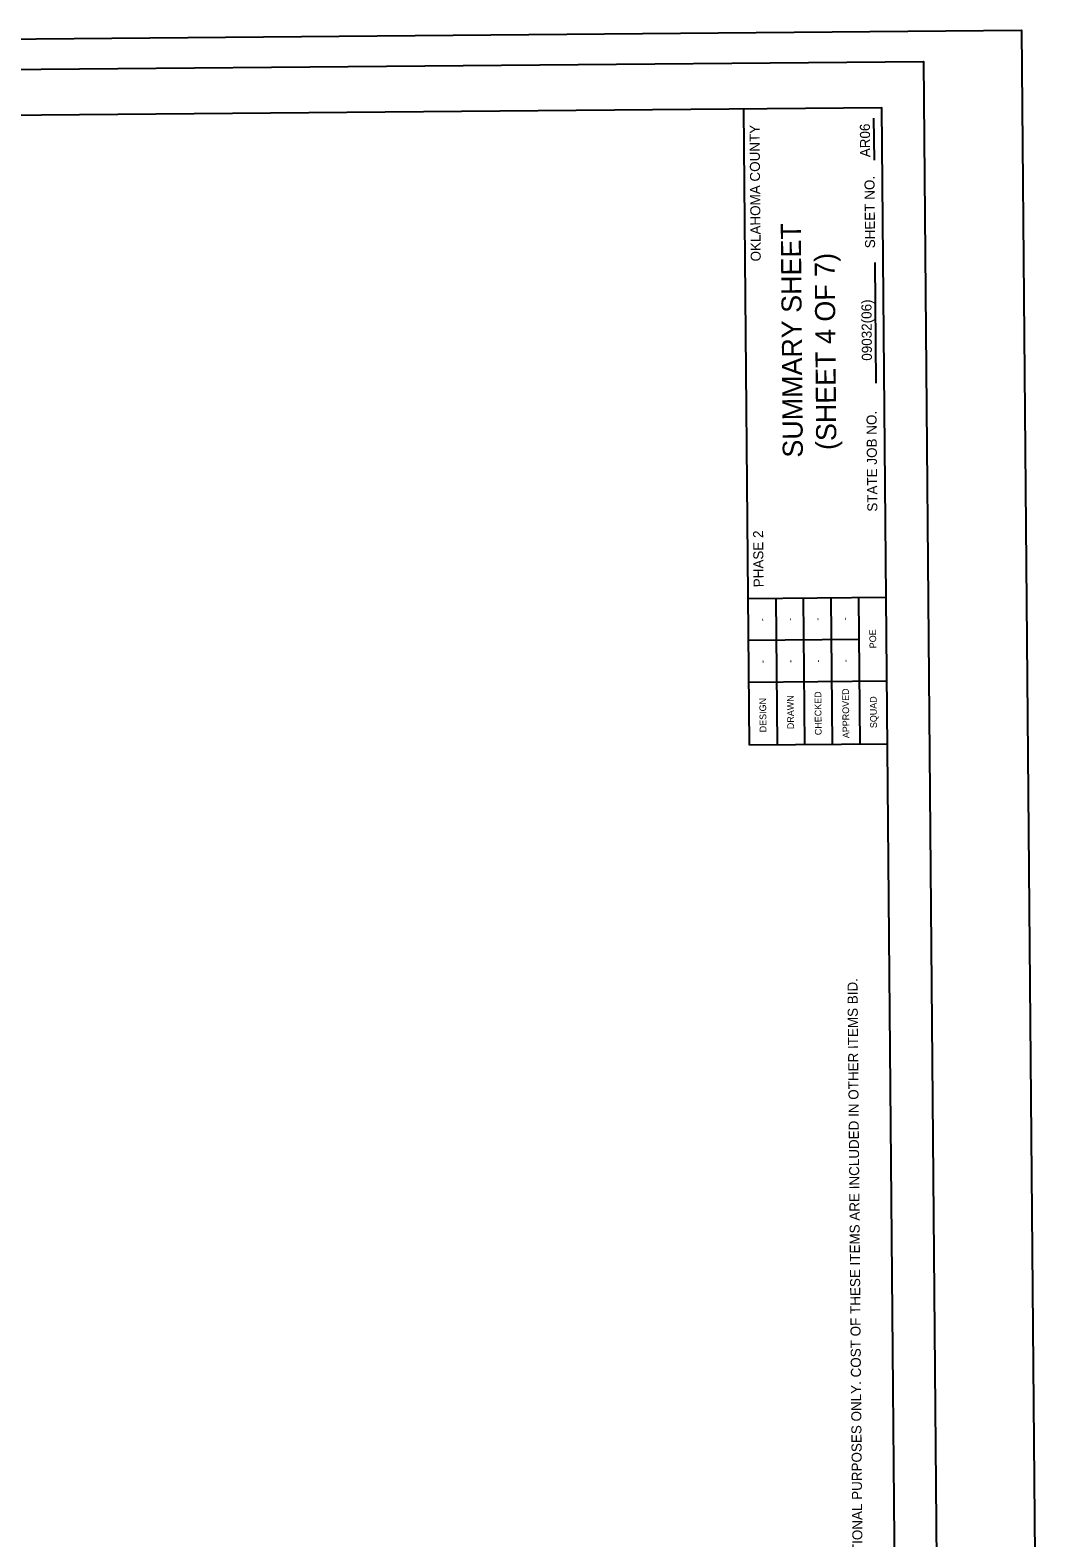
# Model space of a CAD drawing. Extents: x 2151900 to 2151925, y 142567 to 142723.
# Drawn here: x 2151912.93 to 2151925.09, y 142585.4 to 142603.41 of the extents above; entities that cross this region are included whole.
import ezdxf

# ---------------------------------------------------------------- set-up
doc = ezdxf.new("R2010")
doc.units = 0
for name, color, linetype in [('SHT_Plot_Shape_Full', 7, 'Continuous'), ('SHT_Plot_Shape_Half', 7, 'Continuous'), ('SHT_Sheet_Border', 7, 'Continuous'), ('SHT_Standard_Sheet_Lines', 7, 'Continuous'), ('SHT_Standard_Sheet_Txt', 7, 'Continuous'), ('TYP_Typical_Section_Txt', 7, 'Continuous')]:
    doc.layers.add(name, color=color, linetype=linetype)

msp = doc.modelspace()

# ---------------------------------------------------------------- linework, layer by layer
at = {"layer": 'SHT_Plot_Shape_Full'}
msp.add_lwpolyline([(2151901.092, 142567.2), (2151900.777, 142603.199), (2151924.776, 142603.409), (2151925.091, 142567.41)], close=True, dxfattribs=at)
at = {"layer": 'SHT_Plot_Shape_Half'}
msp.add_lwpolyline([(2151901.903, 142568.845), (2151901.605, 142602.844), (2151923.604, 142603.036), (2151923.902, 142569.037)], close=True, dxfattribs=at)
at = {"layer": 'SHT_Sheet_Border'}
for p, q in [((2151921.526, 142594.868), (2151921.459, 142602.467)), ((2151923.16, 142596.632), (2151921.51, 142596.617)), ((2151923.176, 142594.882), (2151921.526, 142594.868))]:
    msp.add_line(p, q, dxfattribs=at)
msp.add_lwpolyline([(2151923.385, 142570.983), (2151923.109, 142602.482), (2151902.11, 142602.298), (2151902.386, 142570.799)], close=True, dxfattribs=at)
at = {"layer": 'SHT_Standard_Sheet_Lines'}
for p, q in [((2151923.019, 142601.856), (2151923.014, 142602.359)), ((2151923.042, 142599.192), (2151923.029, 142600.632)), ((2151922.835, 142596.129), (2151921.514, 142596.118)), ((2151923.169, 142595.632), (2151921.518, 142595.618))]:
    msp.add_line(p, q, dxfattribs=at)
for points in [[(2151921.84, 142596.62), (2151921.856, 142594.871)], [(2151922.17, 142596.623), (2151922.186, 142594.873)], [(2151922.5, 142596.626), (2151922.516, 142594.876)], [(2151922.83, 142596.629), (2151922.846, 142594.879)]]:
    msp.add_lwpolyline(points, dxfattribs=at)

# ---------------------------------------------------------------- texts
at = {"layer": 'SHT_Standard_Sheet_Txt'}
for s, height, p in [('OKLAHOMA COUNTY', 0.12, (2151921.662, 142600.647)), ('AR06', 0.12, (2151922.969, 142601.892)), ('SHEET NO. ', 0.12, (2151923.028, 142600.804)), ('SUMMARY SHEET', 0.24, (2151922.165, 142598.304)), ('(SHEET 4 OF 7)', 0.24, (2151922.565, 142598.395)), ('09032(06)', 0.12, (2151922.99, 142599.461)), ('STATE JOB NO.', 0.12, (2151923.055, 142597.658)), ('PHASE 2', 0.12, (2151921.696, 142596.755)), ('-', 0.08, (2151921.717, 142596.35)), ('-', 0.08, (2151922.047, 142596.353)), ('-', 0.08, (2151922.377, 142596.356)), ('-', 0.08, (2151922.708, 142596.359)), ('POE', 0.08, (2151923.041, 142596.026)), ('-', 0.08, (2151921.721, 142595.85)), ('-', 0.08, (2151922.052, 142595.853)), ('-', 0.08, (2151922.382, 142595.856)), ('-', 0.08, (2151922.712, 142595.859)), ('CHECKED', 0.08, (2151922.389, 142594.988)), ('APPROVED', 0.08, (2151922.72, 142594.952)), ('DESIGN', 0.08, (2151921.729, 142595.022)), ('DRAWN', 0.08, (2151922.059, 142595.06)), ('SQUAD', 0.08, (2151923.049, 142595.072))]:
    msp.add_text(s, height=height, rotation=90.5015, dxfattribs=at).set_placement(p)
at = {"layer": 'TYP_Typical_Section_Txt'}
msp.add_text('(1) QUANTITIES SHOWN ARE FOR INFORMATIONAL PURPOSES ONLY. COST OF THESE ITEMS ARE INCLUDED IN OTHER ITEMS BID.', height=0.12, rotation=90.5015, dxfattribs=at).set_placement((2151922.907, 142581.825))

doc.saveas('drawing.dxf')
